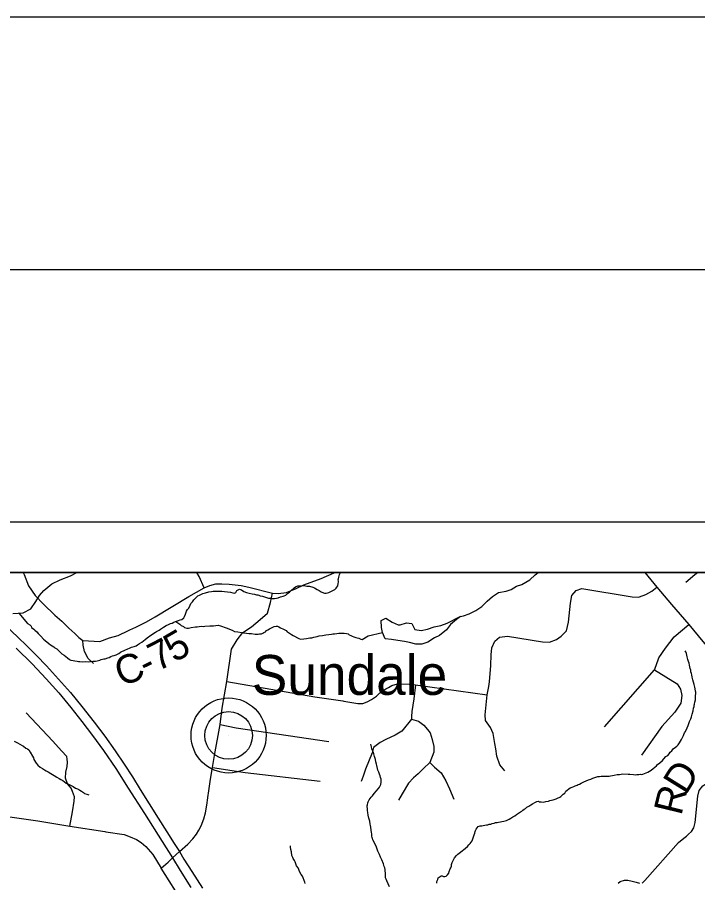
# Model space of a CAD drawing. Extents: x 44.2 to 78.2, y 4.5 to 26.5.
# Drawn here: x 50.361 to 51.71, y 24.786 to 26.501 of the extents above; entities that cross this region are included whole.
import ezdxf

# ---------------------------------------------------------------- set-up
doc = ezdxf.new("R2010")
doc.units = 0
for name, color, linetype in [('GM_X_County_Road', 7, 'Continuous'), ('GM_X_County_Road_Text', 7, 'Continuous'), ('GM_X_Interstate_Route', 7, 'Continuous'), ('GM_X_Minor_Lake', 7, 'Continuous'), ('GM_X_Minor_River', 7, 'Continuous'), ('GM_X_Rail_Line', 7, 'Continuous'), ('GM_X_Township_Road', 7, 'Continuous'), ('GM_X_Township_Road_Text', 7, 'Continuous'), ('GM_X_Unincorporated', 7, 'Continuous'), ('GM_X_Unincorporated_Location', 7, 'Continuous'), ('GM_X_Unincorporated_Text', 7, 'Continuous'), ('SH_Border', 7, 'Continuous'), ('SH_Cut_Line', 7, 'Continuous'), ('SH_Data', 7, 'Continuous')]:
    doc.layers.add(name, color=color, linetype=linetype)

msp = doc.modelspace()

# ---------------------------------------------------------------- linework, layer by layer
at = {"layer": 'GM_X_County_Road'}
for points in [[(50.3724, 25.4014), (50.3742, 25.3973), (50.3828, 25.3746), (50.3961, 25.3556), (50.4127, 25.3383), (50.4353, 25.3164), (50.449, 25.3049), (50.4627, 25.2908), (50.4745, 25.28), (50.4828, 25.2725), (50.4907, 25.2662), (50.5242, 25.2646), (50.5437, 25.2718), (50.5608, 25.2764), (50.5644, 25.2782)], [(50.5644, 25.2782), (50.5769, 25.2844), (50.5839, 25.2876), (50.5953, 25.2928), (50.6167, 25.3037), (50.6336, 25.3133), (50.7006, 25.3536), (50.7311, 25.3708), (50.7421, 25.3752), (50.754, 25.3784), (50.7662, 25.3789), (50.7807, 25.378), (50.8043, 25.3757), (50.8194, 25.3723), (50.8666, 25.3602), (50.8779, 25.3593), (50.8946, 25.3617), (50.9132, 25.3694), (50.9289, 25.3769), (50.9629, 25.389), (50.9888, 25.4008), (50.9899, 25.4014)], [(51.6049, 25.4014), (51.6287, 25.372), (51.6579, 25.338), (51.6921, 25.2979), (51.7201, 25.2645), (51.7412, 25.2401), (51.7735, 25.1995), (51.8263, 25.1325), (51.8542, 25.0979), (51.87, 25.0777), (51.8816, 25.0634), (51.8971, 25.0442), (51.9227, 25.0131), (51.9474, 24.9822), (51.9741, 24.9494), (51.9926, 24.9264), (52.0075, 24.9082), (52.0309, 24.8802), (52.0563, 24.851), (52.0672, 24.838), (52.0823, 24.8205), (52.0953, 24.8055), (52.1082, 24.791), (52.1357, 24.7596)], [(50.7381, 24.9543), (50.7383, 24.9553), (50.7403, 24.9686), (50.7437, 24.9913), (50.7477, 25.0146), (50.7513, 25.0384), (50.7627, 25.0997), (50.7671, 25.1323), (50.7757, 25.1849), (50.7851, 25.2489), (50.7964, 25.2675), (50.8077, 25.282), (50.8247, 25.2933), (50.8424, 25.3078), (50.8569, 25.3207), (50.8626, 25.3417), (50.8666, 25.3602)], [(50.5118, 25.2211), (50.5014, 25.231), (50.4936, 25.2446), (50.4911, 25.2572), (50.4907, 25.2662)], [(50.6989, 24.8631), (50.7087, 24.8731), (50.7158, 24.8828), (50.7204, 24.8903), (50.7252, 24.8994), (50.7304, 24.9129), (50.7334, 24.9251), (50.7361, 24.9403), (50.7381, 24.9543)], [(50.6961, 24.6507), (50.6974, 24.6636), (50.7006, 24.6852), (50.7018, 24.708), (50.6986, 24.724), (50.6902, 24.7449), (50.6457, 24.8153), (50.6594, 24.8273), (50.6684, 24.8359), (50.6821, 24.8482), (50.6989, 24.8631)]]:
    msp.add_lwpolyline(points, dxfattribs=at)
at = {"layer": 'GM_X_Interstate_Route'}
for points in [[(50.3279, 25.3049), (50.3611, 25.274), (50.3804, 25.2553), (50.3987, 25.237), (50.4185, 25.2164), (50.4425, 25.19), (50.4658, 25.1633), (50.4886, 25.1354), (50.5129, 25.1048), (50.5338, 25.0768), (50.5545, 25.0476), (50.5724, 25.0211), (50.5887, 24.9961), (50.6043, 24.9712), (50.6221, 24.9425), (50.6401, 24.9141), (50.6573, 24.887), (50.6718, 24.8638), (50.6821, 24.8482), (50.691, 24.8333), (50.7067, 24.8086), (50.7277, 24.7754)], [(50.3584, 25.2515), (50.3899, 25.2199), (50.4179, 25.1904), (50.4426, 25.1624), (50.4667, 25.1334), (50.4885, 25.1062), (50.5097, 25.0784), (50.5315, 25.0486), (50.5559, 25.0127), (50.5807, 24.974), (50.6127, 24.9233), (50.6475, 24.8681), (50.6684, 24.8359), (50.6838, 24.8106), (50.7048, 24.7772)]]:
    msp.add_lwpolyline(points, dxfattribs=at)
at = {"layer": 'GM_X_Minor_Lake'}
for points in [[(51.2393, 25.314), (51.2315, 25.3078), (51.2195, 25.2978), (51.2114, 25.2877), (51.1975, 25.2766), (51.1879, 25.2719), (51.1744, 25.2634), (51.1629, 25.2591), (51.1507, 25.2594), (51.1379, 25.2627), (51.1281, 25.2644), (51.1152, 25.2662), (51.1027, 25.2687), (51.0902, 25.2697), (51.0847, 25.2824), (51.0826, 25.2919), (51.0818, 25.306), (51.0914, 25.3104), (51.1038, 25.3025), (51.1158, 25.2973)], [(51.1158, 25.2973), (51.1196, 25.2972), (51.1322, 25.3015), (51.1429, 25.3002), (51.1491, 25.2879), (51.1616, 25.2865), (51.1742, 25.2889), (51.1872, 25.2932), (51.2005, 25.2963), (51.2128, 25.3006), (51.239, 25.314)]]:
    msp.add_lwpolyline(points, dxfattribs=at)
at = {"layer": 'GM_X_Minor_River'}
for points in [[(50.3516, 25.3202), (50.3622, 25.3204), (50.3721, 25.3214), (50.3875, 25.3294), (50.3973, 25.3437), (50.4043, 25.3557), (50.4129, 25.3658), (50.4288, 25.3788), (50.4453, 25.3869), (50.4663, 25.3948), (50.4783, 25.4014)], [(50.766, 25.364), (50.7716, 25.3634), (50.7834, 25.362), (50.7879, 25.3611), (50.7913, 25.3603), (50.794, 25.3613), (50.796, 25.3658), (50.8014, 25.368), (50.8048, 25.3668), (50.81, 25.3632), (50.8149, 25.3616), (50.8205, 25.3599), (50.8262, 25.359), (50.8311, 25.3581), (50.8349, 25.3572), (50.8372, 25.3568), (50.8398, 25.356), (50.8421, 25.3552), (50.847, 25.3543), (50.8504, 25.3527), (50.8545, 25.3514), (50.8587, 25.3505), (50.8628, 25.3501), (50.8662, 25.3496), (50.8708, 25.3498), (50.8746, 25.3505), (50.8777, 25.3512), (50.8827, 25.353), (50.8876, 25.3543), (50.8899, 25.3547), (50.893, 25.3561), (50.8961, 25.3598), (50.9004, 25.3624), (50.9035, 25.3653), (50.9093, 25.3705), (50.9124, 25.3727), (50.917, 25.3748), (50.9227, 25.375), (50.9288, 25.3753), (50.9322, 25.3748), (50.9349, 25.3743), (50.9371, 25.3743), (50.9398, 25.3738), (50.9466, 25.3721), (50.9496, 25.3709), (50.9552, 25.3677), (50.9593, 25.3654), (50.9634, 25.3626), (50.9676, 25.3606), (50.9698, 25.3602), (50.9729, 25.3601), (50.9786, 25.3618), (50.9824, 25.3632), (50.9878, 25.3661), (50.9901, 25.3676), (50.9925, 25.3702), (50.9944, 25.3724), (50.996, 25.375), (50.9965, 25.3792), (50.9973, 25.3818), (50.9974, 25.3841), (50.9971, 25.3864), (50.9975, 25.3886), (50.998, 25.392), (50.9996, 25.3969), (51.0005, 25.3996), (51.0014, 25.4014)], [(51.239, 25.314), (51.2452, 25.3154), (51.2567, 25.3193), (51.2697, 25.3259), (51.2817, 25.3337), (51.2922, 25.3445), (51.3026, 25.3534), (51.3149, 25.3612), (51.3302, 25.3643), (51.3397, 25.3675), (51.3505, 25.3738), (51.3612, 25.3774), (51.377, 25.3866), (51.3874, 25.3963), (51.3935, 25.4014)], [(50.3636, 25.3205), (50.3807, 25.3001), (50.3852, 25.2973), (50.3882, 25.295), (50.3889, 25.2919), (50.3934, 25.2891), (50.3956, 25.2872), (50.3993, 25.2837), (50.4022, 25.2802), (50.4074, 25.2747), (50.4122, 25.2693), (50.4159, 25.2665), (50.4234, 25.2603), (50.4264, 25.2579), (50.4294, 25.2559), (50.4327, 25.2536), (50.4353, 25.252), (50.4387, 25.2496), (50.4454, 25.2434), (50.4491, 25.2399), (50.4532, 25.2371), (50.4565, 25.2344), (50.4603, 25.232), (50.464, 25.2289), (50.467, 25.2276), (50.4715, 25.2268), (50.4749, 25.2259), (50.4791, 25.2254), (50.4821, 25.225), (50.4844, 25.2245), (50.4893, 25.2244), (50.4954, 25.2246), (50.5022, 25.2244), (50.506, 25.2251), (50.5106, 25.2254), (50.5133, 25.2253), (50.5159, 25.2256), (50.519, 25.2263), (50.524, 25.2277), (50.527, 25.2287), (50.5324, 25.2301), (50.5347, 25.2304), (50.54, 25.2322), (50.5427, 25.2329), (50.5458, 25.2347), (50.5496, 25.2357), (50.5527, 25.2368), (50.5565, 25.2382), (50.5592, 25.2396), (50.5619, 25.2407), (50.5654, 25.2433), (50.5754, 25.2479), (50.5784, 25.249), (50.5842, 25.2519), (50.5869, 25.253), (50.5923, 25.2547), (50.5961, 25.2561), (50.5992, 25.2579), (50.603, 25.2605), (50.6073, 25.263), (50.6108, 25.2656), (50.6143, 25.2686), (50.6181, 25.2715), (50.6251, 25.277), (50.6344, 25.2828), (50.6367, 25.2843), (50.6417, 25.2872), (50.6444, 25.2886), (50.6467, 25.2905), (50.6502, 25.2926), (50.6556, 25.2959), (50.6606, 25.2984), (50.6641, 25.3003), (50.6679, 25.3009), (50.671, 25.3027), (50.6744, 25.3042), (50.6802, 25.3059), (50.6836, 25.3073), (50.6871, 25.308), (50.6906, 25.3113), (50.6921, 25.3139), (50.6938, 25.3184), (50.6962, 25.3244), (50.6978, 25.3278), (50.7005, 25.3304), (50.703, 25.3364), (50.7046, 25.3398), (50.7081, 25.3431), (50.7108, 25.3468), (50.7136, 25.3502), (50.7167, 25.3527), (50.7186, 25.355), (50.7217, 25.3564), (50.7286, 25.3593), (50.7336, 25.361), (50.7405, 25.3627), (50.7454, 25.3638), (50.7489, 25.364), (50.7527, 25.3643), (50.755, 25.3643), (50.766, 25.364)], [(50.6749, 25.3043), (50.6826, 25.2986), (50.6852, 25.2963), (50.6901, 25.2939), (50.6924, 25.2923), (50.6969, 25.291), (50.6999, 25.291), (50.7026, 25.2913), (50.7056, 25.292), (50.714, 25.2933), (50.7171, 25.2936), (50.7213, 25.2942), (50.7254, 25.2945), (50.7292, 25.2944), (50.7323, 25.2947), (50.7422, 25.2952), (50.7467, 25.2954), (50.7498, 25.2957), (50.754, 25.2964), (50.7589, 25.2966), (50.7638, 25.2957), (50.7676, 25.2941), (50.771, 25.2925), (50.777, 25.2908), (50.7811, 25.2888), (50.7864, 25.2872), (50.7913, 25.2844), (50.7977, 25.2835), (50.8053, 25.2821), (50.8091, 25.2817), (50.8151, 25.2811), (50.8197, 25.2806), (50.825, 25.2801), (50.8322, 25.2792), (50.8379, 25.279), (50.8409, 25.2793), (50.8447, 25.2796), (50.8474, 25.281), (50.8497, 25.2825), (50.8524, 25.2836), (50.8548, 25.2862), (50.8571, 25.2876), (50.8609, 25.2894), (50.8632, 25.2909), (50.8698, 25.2941), (50.874, 25.2951), (50.8762, 25.2947), (50.8793, 25.2935), (50.8826, 25.2915), (50.8882, 25.2887), (50.8935, 25.2863), (50.8957, 25.2839), (50.8983, 25.282), (50.9043, 25.278), (50.9077, 25.276), (50.9189, 25.2701), (50.9219, 25.2692), (50.9288, 25.2694), (50.9337, 25.2701), (50.9406, 25.2714), (50.9444, 25.272), (50.9486, 25.2731), (50.9517, 25.2738), (50.9551, 25.2744), (50.9593, 25.2754), (50.9654, 25.2764), (50.9723, 25.2778), (50.978, 25.2784), (50.9833, 25.279), (50.9864, 25.2793), (50.9894, 25.2796), (50.9944, 25.2802), (50.9982, 25.2809), (51.002, 25.2812), (51.0088, 25.281), (51.013, 25.2805), (51.0164, 25.2793), (51.0186, 25.2777), (51.022, 25.2765), (51.0243, 25.2753), (51.0276, 25.2737), (51.0318, 25.2724), (51.0344, 25.2716), (51.0378, 25.2707), (51.0416, 25.2691), (51.0446, 25.2687)], [(51.0446, 25.2687), (51.0564, 25.2757), (51.0847, 25.2824)], [(51.7056, 25.1542), (51.7059, 25.1637), (51.7055, 25.166), (51.7045, 25.1706), (51.7038, 25.174), (51.7028, 25.179), (51.7014, 25.1836), (51.7, 25.1885), (51.699, 25.1935), (51.698, 25.1981), (51.6973, 25.2007), (51.6963, 25.2046), (51.696, 25.2076), (51.6949, 25.2107), (51.6942, 25.2145), (51.6935, 25.2175), (51.6925, 25.2217), (51.6915, 25.2248), (51.6904, 25.2286), (51.6893, 25.2317), (51.6886, 25.234), (51.6873, 25.2405), (51.6859, 25.2439), (51.6848, 25.2462)], [(51.375, 24.9383), (51.3785, 24.9405), (51.3823, 24.9427), (51.387, 24.9456), (51.3908, 24.9474), (51.3938, 24.9477), (51.3961, 24.9469), (51.3995, 24.9464), (51.4037, 24.9463), (51.4083, 24.9473), (51.4136, 24.9483), (51.4163, 24.949), (51.4228, 24.9507), (51.4289, 24.9528), (51.4316, 24.9539), (51.4362, 24.9561), (51.4385, 24.9575), (51.4432, 24.9619), (51.4459, 24.9641), (51.4483, 24.9675), (51.4506, 24.9701), (51.4541, 24.9727), (51.4568, 24.9741), (51.4606, 24.9759), (51.4641, 24.9773), (51.4668, 24.9784), (51.4706, 24.9798), (51.4729, 24.9809), (51.4756, 24.982), (51.4783, 24.9834), (51.4814, 24.9852), (51.4841, 24.9863), (51.4883, 24.9881), (51.4929, 24.9902), (51.4975, 24.9916), (51.5017, 24.9934), (51.5094, 24.9962), (51.5117, 24.9969), (51.5147, 24.9972), (51.5182, 24.9975), (51.5269, 24.9973), (51.5341, 24.9975), (51.5368, 24.9982), (51.5406, 24.9988), (51.544, 24.9995), (51.5502, 25.0009), (51.5543, 25.0011), (51.5612, 25.0021), (51.5715, 25.0018), (51.5752, 25.0014), (51.5821, 25.0008), (51.5859, 25.0003), (51.5893, 25.0006), (51.5931, 25.0009), (51.5961, 25.0012), (51.5984, 25.0011), (51.6007, 25.0014), (51.6076, 25.0043), (51.6107, 25.0057), (51.6138, 25.0076), (51.6172, 25.0097), (51.6215, 25.013), (51.6277, 25.0178), (51.6297, 25.0208), (51.6347, 25.0241), (51.6401, 25.0289), (51.6425, 25.0318), (51.6464, 25.0363), (51.6506, 25.0388), (51.653, 25.0418), (51.6553, 25.0448), (51.6581, 25.0477), (51.6612, 25.0515), (51.6655, 25.0548), (51.6686, 25.057), (51.6709, 25.0596), (51.6737, 25.0637), (51.6757, 25.0666), (51.6773, 25.07), (51.6801, 25.0752), (51.6813, 25.0779), (51.6825, 25.0801), (51.6837, 25.0831), (51.6853, 25.0861), (51.6885, 25.0936), (51.6905, 25.0977), (51.6921, 25.1022), (51.6937, 25.106), (51.695, 25.1086), (51.6958, 25.1109), (51.697, 25.1131), (51.6974, 25.1154), (51.6987, 25.1207), (51.7004, 25.1271), (51.7016, 25.132), (51.7025, 25.1354), (51.7029, 25.138), (51.7034, 25.1403), (51.7042, 25.144), (51.7051, 25.1486), (51.7056, 25.1542)], [(50.3543, 25.0671), (50.361, 25.0635), (50.3659, 25.0607), (50.3704, 25.0583), (50.3726, 25.0567), (50.3775, 25.0532), (50.3805, 25.0516), (50.3831, 25.0496), (50.3864, 25.0454), (50.3907, 25.0373), (50.3926, 25.0338), (50.3936, 25.0308), (50.398, 25.0231), (50.4013, 25.0192), (50.4061, 25.0157), (50.4106, 25.0125), (50.4147, 25.0101), (50.4181, 25.0081), (50.4219, 25.0061), (50.4271, 25.0026), (50.4334, 24.9986), (50.4391, 24.9954), (50.4436, 24.993), (50.4469, 24.9907), (50.4507, 24.9887), (50.4574, 24.984), (50.4623, 24.9819), (50.466, 24.9799), (50.4712, 24.9768), (50.4757, 24.9736), (50.4802, 24.9724), (50.4825, 24.9708), (50.4847, 24.97), (50.4881, 24.9676), (50.4915, 24.9649), (50.4941, 24.9633), (50.4986, 24.962), (50.5024, 24.9608)], [(51.0749, 25.0129), (51.0732, 25.0187), (51.0725, 25.0213), (51.0715, 25.0259), (51.0705, 25.0309), (51.0691, 25.0366), (51.0673, 25.042), (51.0659, 25.0458), (51.0648, 25.0481), (51.0638, 25.0519), (51.0627, 25.0554), (51.062, 25.0584), (51.0617, 25.0611)], [(51.0986, 24.7782), (51.0932, 24.7898), (51.0918, 24.7932), (51.0907, 24.7963), (51.0908, 24.802), (51.0905, 24.805), (51.0903, 24.8099), (51.09, 24.8126), (51.0893, 24.816), (51.0882, 24.8187), (51.0868, 24.8241), (51.0832, 24.8318), (51.0807, 24.8368), (51.0786, 24.8421), (51.0757, 24.8486), (51.0725, 24.8567), (51.0693, 24.8644), (51.0656, 24.8713), (51.0646, 24.874), (51.0642, 24.8763), (51.0635, 24.8786), (51.0636, 24.8808), (51.0633, 24.8831), (51.063, 24.8862), (51.0619, 24.8904), (51.0613, 24.8968), (51.061, 24.8999), (51.0603, 24.9022), (51.0594, 24.9086), (51.0576, 24.914), (51.0566, 24.9205), (51.0556, 24.9258), (51.055, 24.9296), (51.0547, 24.9334), (51.0544, 24.9365), (51.0544, 24.9387), (51.0549, 24.941), (51.0553, 24.9444), (51.0562, 24.9467), (51.0585, 24.9508), (51.0625, 24.956), (51.0648, 24.9586), (51.0664, 24.9608), (51.0691, 24.9638), (51.0723, 24.9675), (51.077, 24.9734), (51.0786, 24.976), (51.0801, 24.9783), (51.0817, 24.9813), (51.0822, 24.9858), (51.0819, 24.9896), (51.082, 24.9919), (51.0809, 24.9946), (51.0799, 24.9984), (51.0785, 25.0018), (51.0774, 25.0057), (51.0756, 25.0095), (51.0749, 25.0129)], [(51.1922, 24.7857), (51.1927, 24.7891), (51.1943, 24.7928), (51.1951, 24.7958), (51.2009, 24.7998), (51.2032, 24.7998), (51.2055, 24.799), (51.2081, 24.7989), (51.2108, 24.7992), (51.2139, 24.8018), (51.2159, 24.8051), (51.2171, 24.8089), (51.2191, 24.8138), (51.2203, 24.816), (51.2212, 24.8194), (51.2216, 24.8228), (51.2229, 24.8266), (51.2241, 24.8288), (51.2261, 24.8333), (51.2277, 24.8359), (51.2316, 24.84), (51.2343, 24.843), (51.237, 24.8452), (51.2394, 24.847), (51.2432, 24.85), (51.2456, 24.8518), (51.2494, 24.8547), (51.2533, 24.8584), (51.256, 24.8614), (51.2584, 24.864), (51.2607, 24.8666), (51.2623, 24.8692), (51.264, 24.8733), (51.2652, 24.8775), (51.2664, 24.8812), (51.2677, 24.8846), (51.2685, 24.8876), (51.2693, 24.8899), (51.2701, 24.8925), (51.2721, 24.8951), (51.2744, 24.8977), (51.2783, 24.8991), (51.2817, 24.8994), (51.2844, 24.9001), (51.2878, 24.9004), (51.2909, 24.9011), (51.2935, 24.9014), (51.2962, 24.9021), (51.2993, 24.9027), (51.3023, 24.9038), (51.3058, 24.9045), (51.3088, 24.9055), (51.3119, 24.9058), (51.3149, 24.9065), (51.3184, 24.9072), (51.3214, 24.9075), (51.3252, 24.9081), (51.3306, 24.9099), (51.3333, 24.9109), (51.336, 24.9124), (51.3394, 24.9146), (51.3433, 24.9168), (51.3468, 24.9189), (51.3506, 24.9215), (51.3545, 24.9244), (51.358, 24.9266), (51.3607, 24.9284), (51.363, 24.9299), (51.3657, 24.9321), (51.3684, 24.9336), (51.3711, 24.9358), (51.375, 24.9383)], [(50.9313, 24.7849), (50.9306, 24.7876), (50.9291, 24.7906), (50.9277, 24.796), (50.9263, 24.7991), (50.9234, 24.8026), (50.9208, 24.8072), (50.9176, 24.816), (50.9143, 24.8199), (50.9118, 24.8279), (50.91, 24.8306), (50.9078, 24.8341), (50.9067, 24.8364), (50.9046, 24.8406), (50.904, 24.8478), (50.903, 24.8524), (50.9023, 24.8566), (50.902, 24.8596)]]:
    msp.add_lwpolyline(points, dxfattribs=at)
at = {"layer": 'GM_X_Rail_Line'}
msp.add_lwpolyline([(53.1359, 18.9756), (53.1359, 25.4014), (48.0411, 25.4014)], dxfattribs=at)
at = {"layer": 'GM_X_Township_Road'}
for points in [[(50.7311, 25.3708), (50.7214, 25.3931), (50.7163, 25.4014)], [(51.686, 25.3819), (51.7043, 25.397), (51.7096, 25.4014)], [(51.2925, 25.1589), (51.2956, 25.1755), (51.2969, 25.1846), (51.2992, 25.2166), (51.3003, 25.2382), (51.3018, 25.2522), (51.3073, 25.2653), (51.3168, 25.273), (51.3326, 25.2748), (51.4018, 25.2638), (51.4161, 25.2631), (51.4297, 25.2683), (51.4388, 25.2751), (51.4494, 25.2858), (51.4538, 25.303), (51.4575, 25.3404), (51.4604, 25.3554), (51.4685, 25.3653), (51.4802, 25.3693), (51.5796, 25.3528), (51.5932, 25.3526), (51.5941, 25.353)], [(51.5941, 25.353), (51.6067, 25.3576), (51.6185, 25.3644), (51.6287, 25.372)], [(51.6274, 25.2171), (51.6329, 25.2321), (51.6456, 25.2514), (51.663, 25.2739), (51.6921, 25.2979)], [(51.5249, 25.0955), (51.6241, 25.2083), (51.6274, 25.2171)], [(51.6241, 25.2083), (51.6688, 25.1805), (51.6758, 25.1702), (51.678, 25.1574), (51.6765, 25.142), (51.6644, 25.1241), (51.6384, 25.0962), (51.5981, 25.0394)], [(50.7757, 25.1849), (50.9504, 25.1546), (51.0063, 25.1466)], [(51.0063, 25.1466), (51.0082, 25.1463), (51.0361, 25.1416), (51.0456, 25.1416), (51.0542, 25.1446), (51.0627, 25.1496), (51.0727, 25.1561), (51.0797, 25.1626), (51.0874, 25.1681), (51.0916, 25.1707), (51.0966, 25.1732), (51.1034, 25.1775), (51.1142, 25.1803), (51.1376, 25.18), (51.1502, 25.1783), (51.2925, 25.1589)], [(51.1502, 25.1783), (51.1469, 25.1505), (51.143, 25.1255), (51.1424, 25.116), (51.1421, 25.1107), (51.123, 25.0865), (51.1098, 25.0785), (51.0915, 25.0704), (51.0798, 25.0645), (51.0666, 25.0546), (51.0639, 25.044), (51.051, 25.0112), (51.0464, 24.9978), (51.0422, 24.987)], [(51.3274, 25.0078), (51.3175, 25.0202), (51.3113, 25.0374), (51.3091, 25.0517), (51.3076, 25.0623), (51.304, 25.0818), (51.2989, 25.0938), (51.289, 25.1081), (51.2882, 25.1188), (51.2903, 25.1392), (51.2925, 25.1589)], [(50.4644, 24.8987), (50.4698, 24.9271), (50.4733, 24.9477), (50.4741, 24.9563), (50.4703, 24.9669), (50.4673, 24.974), (50.4639, 24.978), (50.4602, 24.9824), (50.4561, 24.9937), (50.4566, 25.0052), (50.4593, 25.0165), (50.4603, 25.0255), (50.4597, 25.0314), (50.4585, 25.0363), (50.4479, 25.0475), (50.431, 25.0671), (50.3782, 25.123)], [(51.1421, 25.1107), (51.1558, 25.1063), (51.1666, 25.0986), (51.1741, 25.0902), (51.1789, 25.0832), (51.1835, 25.07), (51.1864, 25.0561), (51.1866, 25.0451), (51.1787, 25.0244), (51.1663, 25.0129), (51.1554, 25.0024), (51.1463, 24.994), (51.1362, 24.9836), (51.1239, 24.9625), (51.1164, 24.9498)], [(50.7627, 25.0997), (50.7946, 25.0931), (50.9782, 25.0663)], [(51.5997, 24.7858), (51.6051, 24.7905), (51.6719, 24.8659), (51.6819, 24.8747), (51.6872, 24.8788), (51.6917, 24.8829), (51.6975, 24.8882), (51.7023, 24.8953), (51.7047, 24.9059), (51.7097, 24.9578), (51.7125, 24.9693), (51.7196, 24.9781), (51.7495, 24.9984), (51.7624, 25.0071), (51.7736, 25.013), (51.786, 25.0202), (51.7939, 25.0256), (51.8028, 25.0303), (51.8533, 25.0626), (51.87, 25.0777)], [(51.1787, 25.0244), (51.1879, 25.0156), (51.2012, 25.0039), (51.2102, 24.9883), (51.2175, 24.9722), (51.2263, 24.9519)], [(50.7477, 25.0146), (50.8124, 25.0045), (50.9611, 24.9874)], [(50.192, 24.9314), (50.1972, 24.9321), (50.2014, 24.9332), (50.2048, 24.9342), (50.209, 24.9349), (50.2151, 24.9352), (50.4016, 24.909), (50.4644, 24.8987), (50.534, 24.8876)], [(50.534, 24.8876), (50.536, 24.8873), (50.5725, 24.8818), (50.5846, 24.8776), (50.5967, 24.8722), (50.6064, 24.8664), (50.6154, 24.8583), (50.6296, 24.842), (50.6457, 24.8153)], [(51.5519, 24.7855), (51.5562, 24.7888), (51.5644, 24.7913), (51.5709, 24.7917), (51.5796, 24.7897), (51.588, 24.7877), (51.5942, 24.7857)]]:
    msp.add_lwpolyline(points, dxfattribs=at)
at = {"layer": 'GM_X_Unincorporated'}
for radius in [0.0744, 0.0472]:
    msp.add_circle((50.7796, 25.0782), radius, dxfattribs=at)
at = {"layer": 'GM_X_Unincorporated_Location'}
msp.add_line((50.7796, 25.0782), (50.7796, 25.0782), dxfattribs=at)
at = {"layer": 'SH_Border'}
msp.add_lwpolyline([(45.7359, 26.0014), (77.7359, 26.0014), (77.7359, 5.0014), (45.7359, 5.0014)], close=True, dxfattribs=at)
at = {"layer": 'SH_Cut_Line'}
msp.add_lwpolyline([(44.2359, 4.5014), (78.2359, 4.5014), (78.2359, 26.5014), (44.2359, 26.5014)], close=True, dxfattribs=at)
msp.add_lwpolyline([(53.1359, 18.6014), (53.1359, 25.4014), (48.0411, 25.4014)], dxfattribs=at)
at = {"layer": 'SH_Data'}
for p, q in [((46.2359, 25.5014), (53.2359, 25.5014)), ((46.3359, 25.4014), (53.1359, 25.4014))]:
    msp.add_line(p, q, dxfattribs=at)

# ---------------------------------------------------------------- texts
at = {"layer": 'GM_X_County_Road_Text'}
for s, rotation, p in [('5', 30.1915, (50.6722, 25.2216)), ('7', 27.2829, (50.6384, 25.2041)), ('C', 19.9718, (50.5663, 25.1746)), ('-', 26.2002, (50.6164, 25.1932))]:
    msp.add_text(s, height=0.0568, rotation=rotation, dxfattribs=at).set_placement(p)
at = {"layer": 'GM_X_Township_Road_Text'}
for s, rotation, p in [('D', 58.1572, (51.6863, 24.9588)), ('R', 76.3717, (51.6771, 24.9179))]:
    msp.add_text(s, height=0.0568, rotation=rotation, dxfattribs=at).set_placement(p)
at = {"layer": 'GM_X_Unincorporated_Text'}
msp.add_text('Sundale', height=0.07898, rotation=0, dxfattribs=at).set_placement((50.8255, 25.1587))

doc.saveas('drawing.dxf')
